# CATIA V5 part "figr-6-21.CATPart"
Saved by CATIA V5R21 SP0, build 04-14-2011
Part number: Part1
Bounding box of the stored display mesh (mm): x 0 to 150, y -70 to 70, z -150 to 69.804
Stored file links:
  D:\CATIA V5R21 E-RESOURCES\CATIA-V5R21\catia-v5r21-prt\c06-catia-v5r21-prt\c06-catia-v5r21-figr-6-21.CATPart
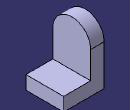
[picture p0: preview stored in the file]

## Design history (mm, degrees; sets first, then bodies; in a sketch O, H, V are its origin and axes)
Body1 (main body)
  Sketch1 on yz-plane, origin (0, 0, 0), H (0, 1, 0), V (0, 0, 1)
    arc A1 centre (0, 0) radius 70 from (70, 0) to (-70, 0) ccw
    point P1 (70, 0)
    point P2 (-70, 0)
    line L1 (-70, 0) -> (-70, -150)
    line L2 (-70, -150) -> (70, -150)
    line L3 (70, -150) -> (70, 0)
    construction circle A2 centre (0, 0) radius 37.5
    radius A1 = 70
    radius A2 = 37.5
    distance O L2 = 150
    coincidence: P1 H, P2 H
    tangency: L1 A1, L3 A1
    horizontal: L2 H
  Pad1: profile Sketch1, direction (1, 0, 0), length 50
  Sketch2 on face of Pad1, origin (50, 0, 0), H (0, 1, 0), V (0, 0, 1)
    line L1 (-70, -150) -> (70, -150)
    line L2 (70, -150) -> (70, -100)
    line L3 (70, -100) -> (-70, -100)
    line L4 (-70, -100) -> (-70, -150)
    reference projected line E1 (-70, -150) -> (70, -150) from edge [face of Pad1 | face of Pad1]
    reference projected line E2 (-70, 0) -> (-70, -150) from edge [face of Pad1 | face of Pad1]
    reference projected line E3 (70, -150) -> (70, 0) from edge [face of Pad1 | face of Pad1]
    length L2 = 50
    horizontal: L1 H, L3 H
    vertical: L2 V, L4 V
    coincidence: L1 E1, E2 L4, L2 E3
  Pad2: profile Sketch2, direction (1, 0, 0), length 100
